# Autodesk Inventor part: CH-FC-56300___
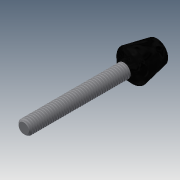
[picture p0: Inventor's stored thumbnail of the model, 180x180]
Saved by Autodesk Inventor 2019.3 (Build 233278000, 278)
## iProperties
Created: 2012-09
Part Number: CH-FC-56300___
Material: Ogólny
Document SubType Name: Modeling
Designer: CADENGINEERING4
Density: 1 g/cm^3
Appearance: Domyślna
Author: CADENGINEERING4
Revision Number: ÈÎºÎ
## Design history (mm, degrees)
feature "NONE"
node "Bryła1"
